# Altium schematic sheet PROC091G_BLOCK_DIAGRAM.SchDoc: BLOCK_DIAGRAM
size 431 x 279 mm; Date: Not shown in title block; ApprovedBy: Not shown in title block; CheckedBy: Not shown in title block; Author: Not shown in title block; CompanyName: Not shown in title block; DrawnBy: Antony/Bala; Engineer: Not shown in title block; Organization: Not shown in title block; Address1: Not shown in title block; Address2: Not shown in title block; Address3: Not shown in title block; Address4: Not shown in title block; DocumentNumber: 1; Revision: Use project parameter SCH_Rev; SheetNumber: 1; SheetTotal: 12; PageSetup: Record=PageOptions¦CenterHorizontal=True¦CenterVertical=True¦PrintScale=1.00¦XCorrection=1.00¦YCorrection=1.00¦PrintKind=0¦BorderSize=5000000¦LeftOffset=0¦BottomOffset=0¦Orientation=2¦PaperLength=1000¦PaperWidth=1000¦Scale=100¦PaperSource=15¦PrintQuality=600¦MediaType=1¦DitherType=10¦PaperKind=Letter¦PrintScaleMode=1
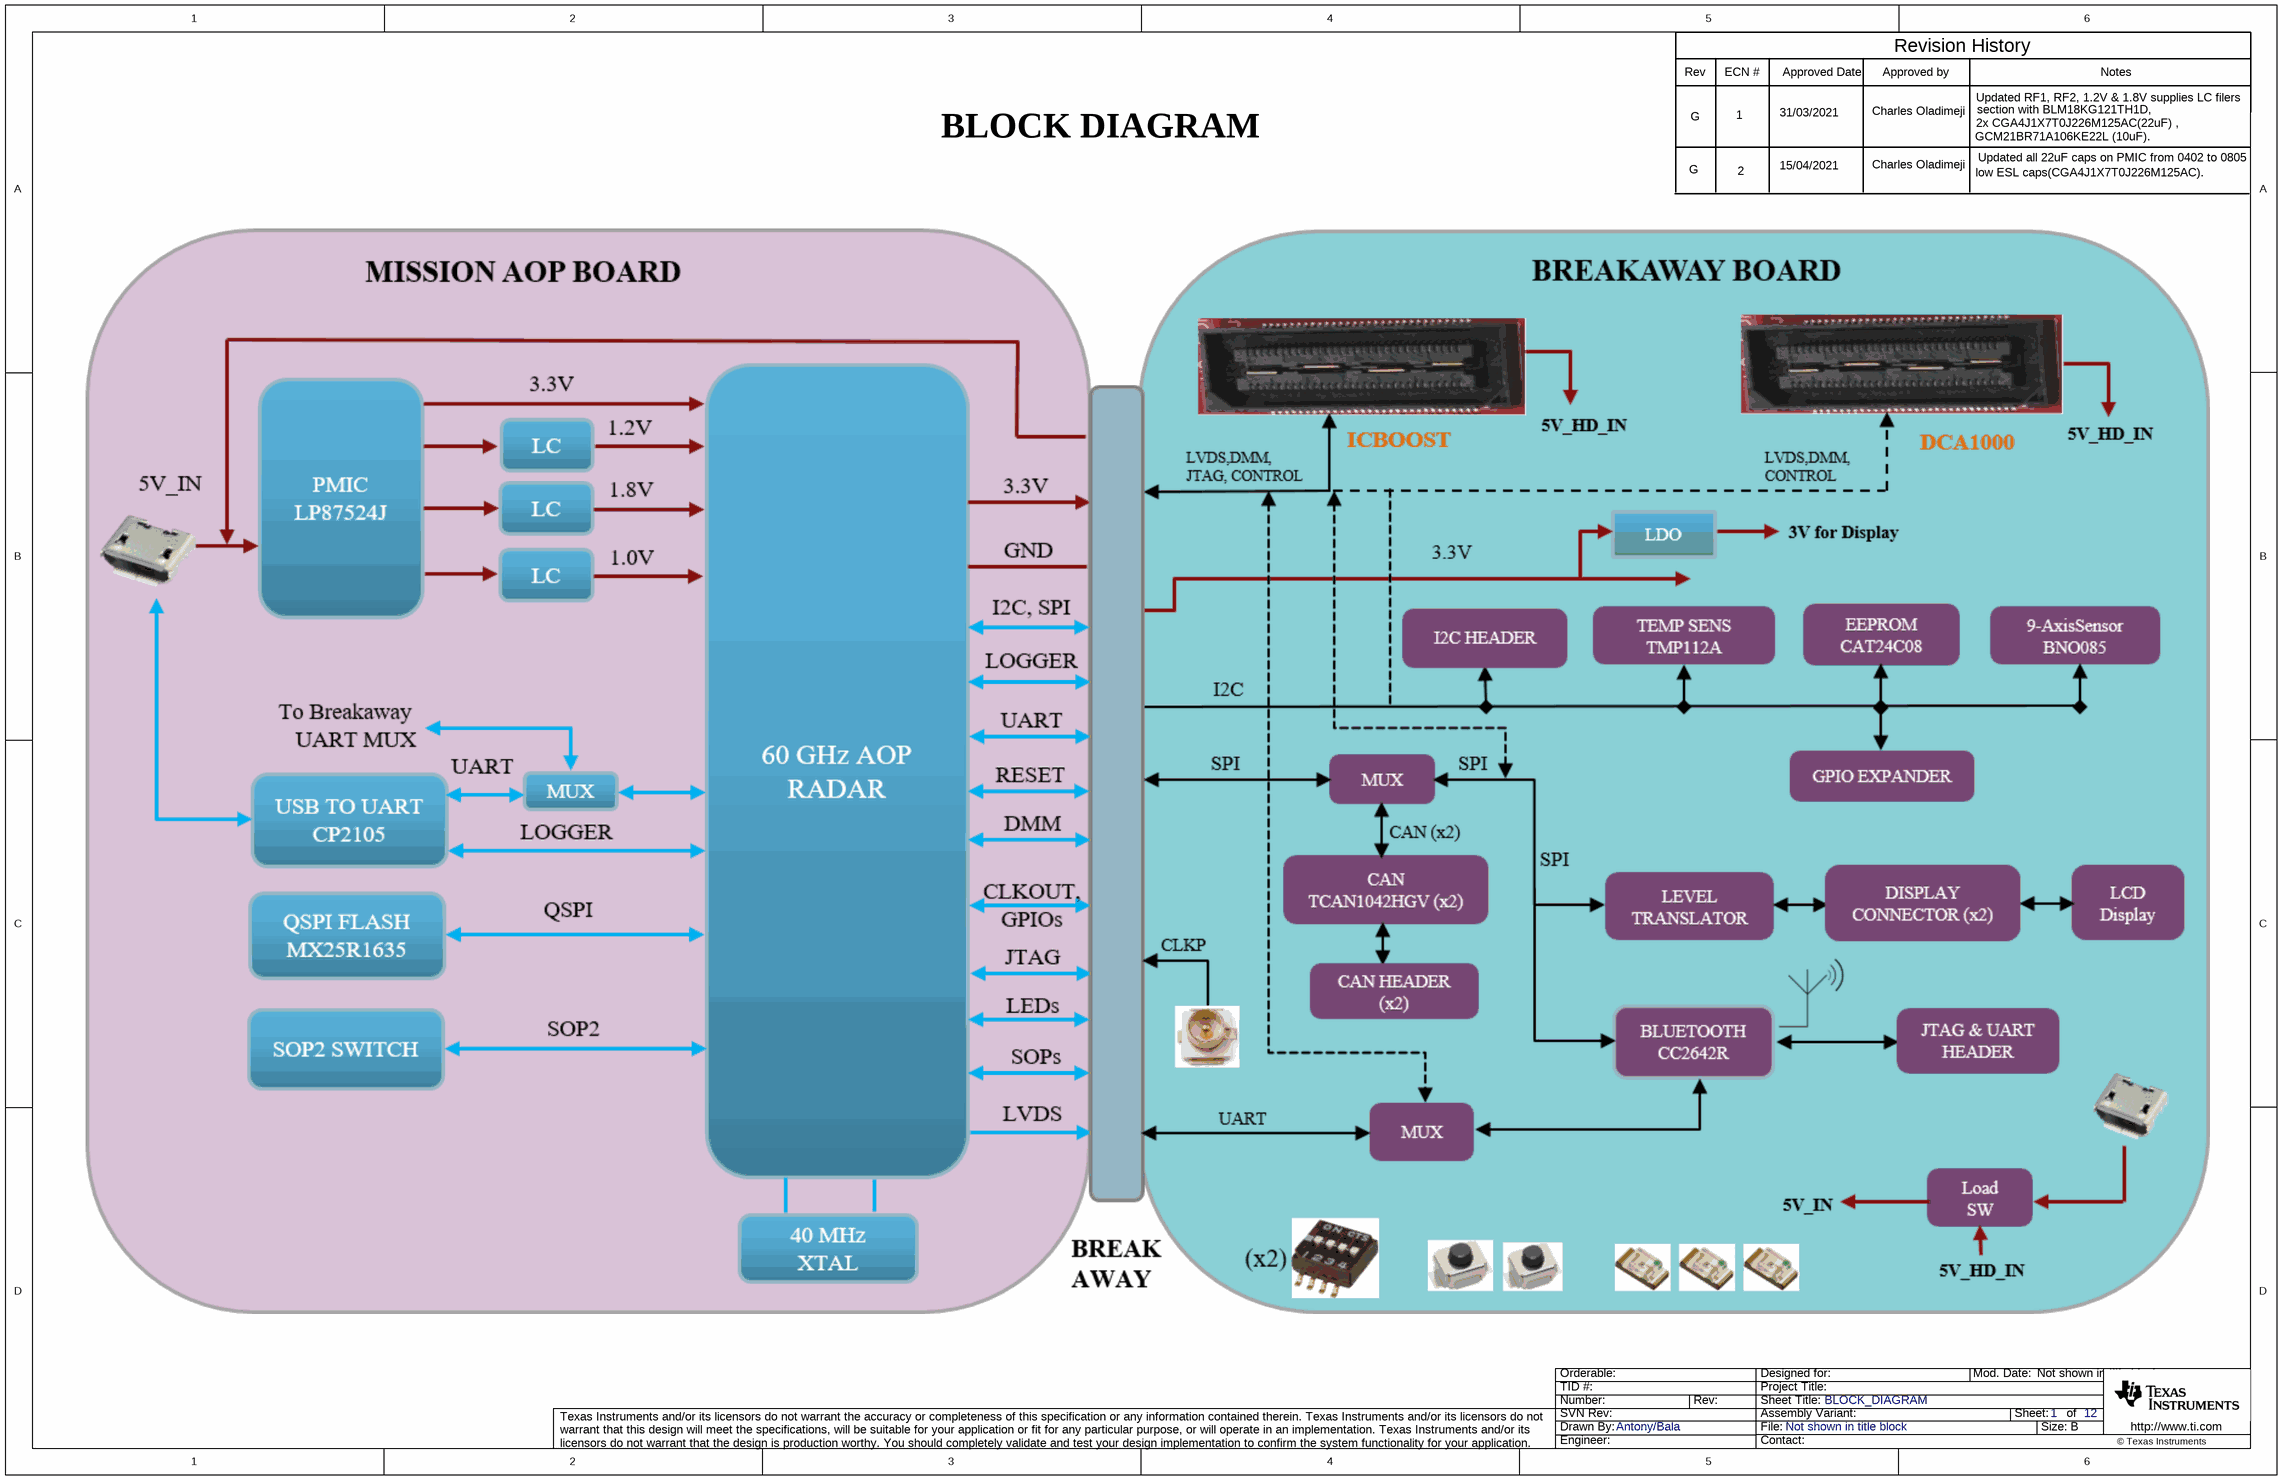
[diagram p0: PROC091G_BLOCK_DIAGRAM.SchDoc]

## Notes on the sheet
- Rev
- ECN #
- Approved Date
- Approved by
- Revision History
- Updated RF1, RF2, 1.2V & 1.8V supplies LC filers
- Notes
- BLOCK DIAGRAM
- G
- 1
- 2
- 31/03/2021
- 15/04/2021
- Charles Oladimeji
- GCM21BR71A106KE22L (10uF).
- section with BLM18KG121TH1D,
- 2x CGA4J1X7T0J226M125AC(22uF) ,
- low ESL caps(CGA4J1X7T0J226M125AC).
- Updated all 22uF caps on PMIC from 0402 to 0805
